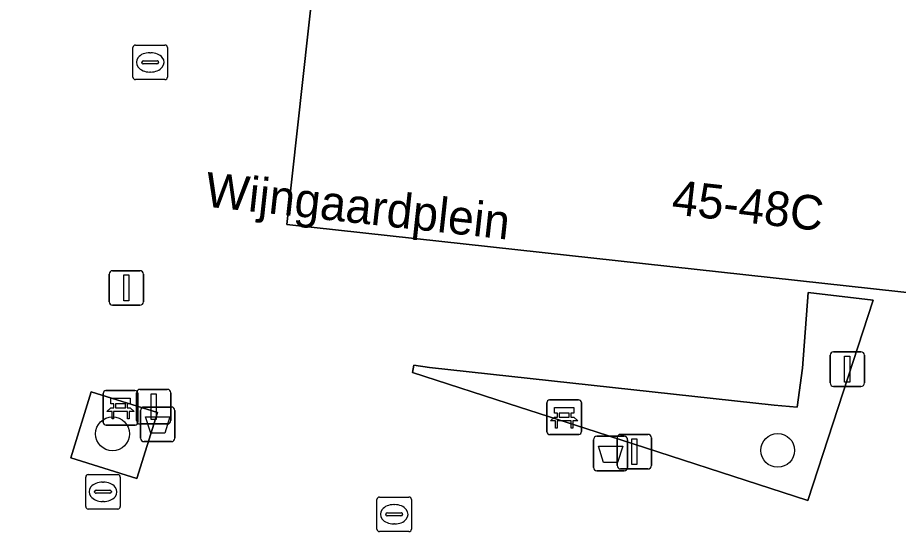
# Model space of a CAD drawing. Extents: x 162026 to 163502, y 387295 to 388169.
# Drawn here: x 162355.04 to 162380.52, y 387587.27 to 387602.42 of the extents above; entities that cross this region are included whole.
import ezdxf

# ---------------------------------------------------------------- set-up
doc = ezdxf.new("R2010")
doc.units = 0
for name, color, linetype in [('IMGEO_Afvalbak', 7, 'Continuous'), ('IMGEO_Bank', 7, 'Continuous'), ('IMGEO_Boom', 7, 'Continuous'), ('IMGEO_Groenvoorziening', 7, 'Continuous'), ('IMGEO_Kolk', 7, 'Continuous'), ('IMGEO_Lichtmast', 7, 'Continuous'), ('IMGEO_Openbare_ruimte_label', 7, 'Continuous'), ('IMGEO_Pand', 7, 'Continuous'), ('IMGEO_Pand_nummerreeks', 7, 'Continuous'), ('IMGEO_Voetpad_open', 7, 'Continuous')]:
    doc.layers.add(name, color=color, linetype=linetype)

msp = doc.modelspace()

# ---------------------------------------------------------------- linework, layer by layer
at = {"layer": 'IMGEO_Afvalbak'}
for p, q in [((162358.598, 387590.256), (162358.598, 387591.056)), ((162358.598, 387591.056), (162358.598, 387590.256)), ((162358.698, 387591.156), (162359.488, 387591.156)), ((162359.488, 387591.156), (162358.698, 387591.156)), ((162359.588, 387591.056), (162359.588, 387590.256)), ((162359.588, 387590.256), (162359.588, 387591.056)), ((162371.795, 387590.31), (162372.585, 387590.31)), ((162372.585, 387590.31), (162371.795, 387590.31)), ((162359.488, 387590.156), (162358.698, 387590.156)), ((162358.698, 387590.156), (162359.488, 387590.156)), ((162371.695, 387589.41), (162371.695, 387590.21)), ((162371.695, 387590.21), (162371.695, 387589.41)), ((162372.685, 387590.21), (162372.685, 387589.41)), ((162372.685, 387589.41), (162372.685, 387590.21)), ((162372.585, 387589.31), (162371.795, 387589.31)), ((162371.795, 387589.31), (162372.585, 387589.31))]:
    msp.add_line(p, q, dxfattribs=at)
for points in [[(162358.741, 387590.87), (162359.445, 387590.87), (162359.296, 387590.4), (162358.89, 387590.4), (162358.741, 387590.87)], [(162371.838, 387590.024), (162372.542, 387590.024), (162372.393, 387589.554), (162371.987, 387589.554), (162371.838, 387590.024)]]:
    msp.add_lwpolyline(points, dxfattribs=at)
for centre, start, end in [((162358.698, 387591.056), 90, 180), ((162358.698, 387591.056), 90, 180), ((162359.488, 387591.056), 0, 90), ((162359.488, 387591.056), 360, 90), ((162358.698, 387590.256), 180, 270), ((162358.698, 387590.256), 180, 270), ((162359.488, 387590.256), 270, 0), ((162359.488, 387590.256), 270, 0), ((162371.795, 387590.21), 90, 180), ((162371.795, 387590.21), 90, 180), ((162372.585, 387590.21), 0, 90), ((162372.585, 387590.21), 360, 90), ((162371.795, 387589.41), 180, 270), ((162371.795, 387589.41), 180, 270), ((162372.585, 387589.41), 270, 0), ((162372.585, 387589.41), 270, 0)]:
    msp.add_arc(centre, 0.1, start, end, dxfattribs=at)
at = {"layer": 'IMGEO_Bank'}
for p, q in [((162357.519, 387590.709), (162357.519, 387591.55)), ((162357.519, 387591.55), (162357.519, 387590.709)), ((162357.594, 387591.634), (162358.435, 387591.634)), ((162358.435, 387591.634), (162357.594, 387591.634)), ((162358.519, 387591.559), (162358.519, 387590.718)), ((162358.519, 387590.718), (162358.519, 387591.559)), ((162357.828, 387591.14), (162357.828, 387591.246)), ((162357.872, 387591.246), (162357.872, 387591.14)), ((162358.16, 387591.252), (162357.878, 387591.252)), ((162358.166, 387591.14), (162358.166, 387591.246)), ((162358.21, 387591.246), (162358.21, 387591.14)), ((162370.349, 387590.437), (162370.349, 387591.278)), ((162370.349, 387591.278), (162370.349, 387590.437)), ((162370.424, 387591.362), (162371.265, 387591.362)), ((162371.265, 387591.362), (162370.424, 387591.362)), ((162371.349, 387591.287), (162371.349, 387590.446)), ((162371.349, 387590.446), (162371.349, 387591.287)), ((162358.216, 387591.032), (162357.823, 387591.032)), ((162357.878, 387591.134), (162358.16, 387591.134)), ((162371.046, 387590.76), (162370.653, 387590.76)), ((162370.658, 387590.868), (162370.658, 387590.974)), ((162370.702, 387590.974), (162370.702, 387590.868)), ((162370.99, 387590.98), (162370.708, 387590.98)), ((162370.708, 387590.862), (162370.99, 387590.862)), ((162370.996, 387590.868), (162370.996, 387590.974)), ((162371.04, 387590.974), (162371.04, 387590.868)), ((162358.444, 387590.634), (162357.603, 387590.634)), ((162357.603, 387590.634), (162358.444, 387590.634)), ((162371.274, 387590.362), (162370.433, 387590.362)), ((162370.433, 387590.362), (162371.274, 387590.362))]:
    msp.add_line(p, q, dxfattribs=at)
for points in [[(162357.822, 387591.252), (162357.736, 387591.252), (162357.736, 387591.413), (162358.299, 387591.413), (162358.299, 387591.252), (162358.216, 387591.252)], [(162357.766, 387591.032), (162357.624, 387591.032), (162357.736, 387591.134), (162357.822, 387591.134)], [(162357.816, 387591.025), (162357.816, 387590.818), (162357.773, 387590.818), (162357.773, 387591.025)], [(162358.216, 387591.134), (162358.299, 387591.134), (162358.411, 387591.032), (162358.272, 387591.032)], [(162358.266, 387591.025), (162358.266, 387590.818), (162358.222, 387590.818), (162358.222, 387591.025)], [(162370.652, 387590.98), (162370.566, 387590.98), (162370.566, 387591.141), (162371.129, 387591.141), (162371.129, 387590.98), (162371.046, 387590.98)], [(162370.596, 387590.76), (162370.454, 387590.76), (162370.566, 387590.862), (162370.652, 387590.862)], [(162370.646, 387590.753), (162370.646, 387590.546), (162370.603, 387590.546), (162370.603, 387590.753)], [(162371.046, 387590.862), (162371.129, 387590.862), (162371.241, 387590.76), (162371.102, 387590.76)], [(162371.096, 387590.753), (162371.096, 387590.546), (162371.052, 387590.546), (162371.052, 387590.753)]]:
    msp.add_lwpolyline(points, dxfattribs=at)
for centre, radius, start, end in [((162357.597, 387591.556), 0.0779, 92.4484, 184.2845), ((162357.597, 387591.556), 0.0779, 92.4484, 184.2845), ((162358.441, 387591.556), 0.0779, 2.4484, 94.2845), ((162358.441, 387591.556), 0.0779, 2.4484, 94.2845), ((162357.821, 387591.245), 0.00671, 2.8957, 87.1043), ((162357.878, 387591.245), 0.00671, 92.8957, 177.1043), ((162358.16, 387591.245), 0.00671, 2.8957, 87.1043), ((162358.217, 387591.245), 0.00671, 92.8957, 177.1043), ((162370.427, 387591.284), 0.0779, 92.4484, 184.2845), ((162370.427, 387591.284), 0.0779, 92.4484, 184.2845), ((162371.271, 387591.284), 0.0779, 2.4484, 94.2845), ((162371.271, 387591.284), 0.0779, 2.4484, 94.2845), ((162357.766, 387591.025), 0.00671, 2.8957, 87.1043), ((162357.823, 387591.025), 0.00671, 92.8957, 177.1043), ((162357.821, 387591.141), 0.00671, 272.8957, 357.1043), ((162357.878, 387591.141), 0.00671, 182.8957, 267.1043), ((162358.16, 387591.141), 0.00671, 272.8957, 357.1043), ((162358.217, 387591.141), 0.00671, 182.8957, 267.1043), ((162358.215, 387591.025), 0.00671, 2.8957, 87.1043), ((162358.272, 387591.025), 0.00671, 92.8957, 177.1043), ((162370.596, 387590.753), 0.00671, 2.8957, 87.1043), ((162370.653, 387590.753), 0.00671, 92.8957, 177.1043), ((162370.651, 387590.973), 0.00671, 2.8957, 87.1043), ((162370.651, 387590.869), 0.00671, 272.8957, 357.1043), ((162370.708, 387590.973), 0.00671, 92.8957, 177.1043), ((162370.708, 387590.869), 0.00671, 182.8957, 267.1043), ((162370.99, 387590.973), 0.00671, 2.8957, 87.1043), ((162370.99, 387590.869), 0.00671, 272.8957, 357.1043), ((162371.047, 387590.973), 0.00671, 92.8957, 177.1043), ((162371.047, 387590.869), 0.00671, 182.8957, 267.1043), ((162371.045, 387590.753), 0.00671, 2.8957, 87.1043), ((162371.102, 387590.753), 0.00671, 92.8957, 177.1043), ((162357.597, 387590.712), 0.0779, 182.4484, 274.2845), ((162357.597, 387590.712), 0.0779, 182.4484, 274.2845), ((162358.441, 387590.712), 0.0779, 272.4484, 4.2845), ((162358.441, 387590.712), 0.0779, 272.4484, 4.2845), ((162370.427, 387590.44), 0.0779, 182.4484, 274.2845), ((162370.427, 387590.44), 0.0779, 182.4484, 274.2845), ((162371.271, 387590.44), 0.0779, 272.4484, 4.2845), ((162371.271, 387590.44), 0.0779, 272.4484, 4.2845)]:
    msp.add_arc(centre, radius, start, end, dxfattribs=at)
at = {"layer": 'IMGEO_Boom'}
for centre in [(162357.787, 387590.381), (162377.026, 387589.902)]:
    msp.add_circle(centre, 0.489, dxfattribs=at)
at = {"layer": 'IMGEO_Groenvoorziening'}
for points in [[(162379.786, 387594.25), (162377.908, 387594.474), (162377.743, 387592.285), (162377.591, 387591.152), (162376.927, 387591.209), (162366.953, 387592.298), (162366.502, 387592.368), (162366.467, 387592.152), (162369.557, 387591.156), (162371.779, 387590.44), (162377.899, 387588.449)], [(162356.577, 387589.687), (162358.486, 387589.091), (162359.083, 387591), (162357.173, 387591.596)]]:
    msp.add_lwpolyline(points, close=True, dxfattribs=at)
at = {"layer": 'IMGEO_Kolk'}
for p, q in [((162358.376, 387600.703), (162358.376, 387601.555)), ((162358.451, 387601.629), (162359.303, 387601.629)), ((162359.377, 387601.555), (162359.377, 387600.703)), ((162358.678, 387601.172), (162359.076, 387601.172)), ((162358.864, 387601.409), (162358.889, 387601.409)), ((162358.635, 387601.123), (162358.635, 387601.135)), ((162359.073, 387601.086), (162358.675, 387601.086)), ((162359.119, 387601.135), (162359.119, 387601.123)), ((162358.887, 387600.849), (162358.862, 387600.849)), ((162359.303, 387600.629), (162358.451, 387600.629)), ((162357.085, 387589.204), (162357.937, 387589.204)), ((162357.01, 387588.278), (162357.01, 387589.13)), ((162357.498, 387588.984), (162357.523, 387588.984)), ((162358.011, 387589.13), (162358.011, 387588.278)), ((162357.269, 387588.698), (162357.269, 387588.71)), ((162357.312, 387588.747), (162357.71, 387588.747)), ((162357.753, 387588.71), (162357.753, 387588.698)), ((162357.707, 387588.661), (162357.309, 387588.661)), ((162365.433, 387587.627), (162365.433, 387588.479)), ((162365.508, 387588.553), (162366.36, 387588.553)), ((162366.434, 387588.479), (162366.434, 387587.627)), ((162357.937, 387588.204), (162357.085, 387588.204)), ((162357.521, 387588.424), (162357.496, 387588.424)), ((162365.921, 387588.333), (162365.946, 387588.333)), ((162365.692, 387588.047), (162365.692, 387588.059)), ((162366.13, 387588.01), (162365.732, 387588.01)), ((162365.735, 387588.096), (162366.133, 387588.096)), ((162366.176, 387588.059), (162366.176, 387588.047)), ((162365.944, 387587.773), (162365.919, 387587.773)), ((162366.36, 387587.553), (162365.508, 387587.553))]:
    msp.add_line(p, q, dxfattribs=at)
for points in [[(162358.376, 387600.703), (162358.376, 387601.555)], [(162358.451, 387601.629), (162359.303, 387601.629)], [(162359.377, 387601.555), (162359.377, 387600.703)], [(162359.303, 387600.629), (162358.451, 387600.629)], [(162357.085, 387589.204), (162357.937, 387589.204)], [(162357.01, 387588.278), (162357.01, 387589.13)], [(162358.011, 387589.13), (162358.011, 387588.278)], [(162365.433, 387587.627), (162365.433, 387588.479)], [(162365.508, 387588.553), (162366.36, 387588.553)], [(162366.434, 387588.479), (162366.434, 387587.627)], [(162357.937, 387588.204), (162357.085, 387588.204)], [(162366.36, 387587.553), (162365.508, 387587.553)]]:
    msp.add_lwpolyline(points, dxfattribs=at)
for centre, radius, start, end in [((162358.453, 387601.553), 0.0765, 91.552, 178.448), ((162358.453, 387601.553), 0.0765, 91.552, 178.448), ((162359.301, 387601.553), 0.0765, 1.552, 88.448), ((162359.301, 387601.553), 0.0765, 1.552, 88.448), ((162358.675, 387601.132), 0.0403, 85.8775, 175.7526), ((162359.08, 387601.134), 0.0386, 1.7309, 96.639), ((162358.672, 387601.122), 0.0366, 178.938, 274.7102), ((162359.076, 387601.129), 0.043, 264.8664, 352.4533), ((162358.453, 387600.705), 0.0765, 181.552, 268.448), ((162358.453, 387600.705), 0.0765, 181.552, 268.448), ((162359.301, 387600.705), 0.0765, 271.552, 358.448), ((162359.301, 387600.705), 0.0765, 271.552, 358.448), ((162357.087, 387589.128), 0.0765, 91.552, 178.448), ((162357.087, 387589.128), 0.0765, 91.552, 178.448), ((162357.935, 387589.128), 0.0765, 1.552, 88.448), ((162357.935, 387589.128), 0.0765, 1.552, 88.448), ((162357.309, 387588.707), 0.0403, 85.8775, 175.7526), ((162357.306, 387588.697), 0.0366, 178.938, 274.7102), ((162357.71, 387588.704), 0.043, 264.8664, 352.4533), ((162357.714, 387588.709), 0.0386, 1.7309, 96.639), ((162365.51, 387588.477), 0.0765, 91.552, 178.448), ((162365.51, 387588.477), 0.0765, 91.552, 178.448), ((162366.358, 387588.477), 0.0765, 1.552, 88.448), ((162366.358, 387588.477), 0.0765, 1.552, 88.448), ((162357.087, 387588.28), 0.0765, 181.552, 268.448), ((162357.087, 387588.28), 0.0765, 181.552, 268.448), ((162357.935, 387588.28), 0.0765, 271.552, 358.448), ((162357.935, 387588.28), 0.0765, 271.552, 358.448), ((162365.732, 387588.056), 0.0403, 85.8775, 175.7526), ((162365.729, 387588.046), 0.0366, 178.938, 274.7102), ((162366.133, 387588.053), 0.043, 264.8664, 352.4533), ((162366.137, 387588.058), 0.0386, 1.7309, 96.639), ((162365.51, 387587.629), 0.0765, 181.552, 268.448), ((162365.51, 387587.629), 0.0765, 181.552, 268.448), ((162366.358, 387587.629), 0.0765, 271.552, 358.448), ((162366.358, 387587.629), 0.0765, 271.552, 358.448)]:
    msp.add_arc(centre, radius, start, end, dxfattribs=at)
for centre, major_axis, ratio, start_param, end_param in [((162358.863, 387601.129), (-0.387, 0.002), 0.722429, 4.712389, 7.853982), ((162358.888, 387601.129), (-0.39, 0.002), 0.717154, 1.570796, 4.712389), ((162357.497, 387588.704), (-0.387, 0.002), 0.722429, 4.712389, 7.853982), ((162357.522, 387588.704), (-0.39, 0.002), 0.717154, 1.570796, 4.712389), ((162365.92, 387588.053), (-0.387, 0.002), 0.722429, 4.712389, 7.853982), ((162365.945, 387588.053), (-0.39, 0.002), 0.717154, 1.570796, 4.712389)]:
    msp.add_ellipse(centre, major_axis=major_axis, ratio=ratio, start_param=start_param, end_param=end_param, dxfattribs=at)
at = {"layer": 'IMGEO_Lichtmast'}
for p, q in [((162357.789, 387595.102), (162358.579, 387595.102)), ((162358.579, 387595.102), (162357.789, 387595.102)), ((162357.689, 387594.202), (162357.689, 387595.002)), ((162357.689, 387595.002), (162357.689, 387594.202)), ((162358.679, 387595.002), (162358.679, 387594.202)), ((162358.679, 387594.202), (162358.679, 387595.002)), ((162358.579, 387594.102), (162357.789, 387594.102)), ((162357.789, 387594.102), (162358.579, 387594.102)), ((162378.542, 387591.854), (162378.542, 387592.654)), ((162378.542, 387592.654), (162378.542, 387591.854)), ((162378.642, 387592.754), (162379.432, 387592.754)), ((162379.432, 387592.754), (162378.642, 387592.754)), ((162379.532, 387592.654), (162379.532, 387591.854)), ((162379.532, 387591.854), (162379.532, 387592.654)), ((162379.432, 387591.754), (162378.642, 387591.754)), ((162378.642, 387591.754), (162379.432, 387591.754)), ((162358.481, 387590.767), (162358.481, 387591.567)), ((162358.481, 387591.567), (162358.481, 387590.767)), ((162358.581, 387591.667), (162359.371, 387591.667)), ((162359.371, 387591.667), (162358.581, 387591.667)), ((162359.471, 387591.567), (162359.471, 387590.767)), ((162359.471, 387590.767), (162359.471, 387591.567)), ((162359.371, 387590.667), (162358.581, 387590.667)), ((162358.581, 387590.667), (162359.371, 387590.667)), ((162372.382, 387589.465), (162372.382, 387590.265)), ((162372.382, 387590.265), (162372.382, 387589.465)), ((162372.482, 387590.365), (162373.272, 387590.365)), ((162373.272, 387590.365), (162372.482, 387590.365)), ((162373.372, 387590.265), (162373.372, 387589.465)), ((162373.372, 387589.465), (162373.372, 387590.265)), ((162373.272, 387589.365), (162372.482, 387589.365)), ((162372.482, 387589.365), (162373.272, 387589.365))]:
    msp.add_line(p, q, dxfattribs=at)
for points in [[(162358.109, 387594.977), (162358.259, 387594.977), (162358.259, 387594.227), (162358.109, 387594.227), (162358.109, 387594.977)], [(162378.962, 387592.629), (162379.112, 387592.629), (162379.112, 387591.879), (162378.962, 387591.879), (162378.962, 387592.629)], [(162358.901, 387591.542), (162359.051, 387591.542), (162359.051, 387590.792), (162358.901, 387590.792), (162358.901, 387591.542)], [(162372.802, 387590.24), (162372.952, 387590.24), (162372.952, 387589.49), (162372.802, 387589.49), (162372.802, 387590.24)]]:
    msp.add_lwpolyline(points, dxfattribs=at)
for centre, start, end in [((162357.789, 387595.002), 90, 180), ((162357.789, 387595.002), 90, 180), ((162358.579, 387595.002), 0, 90), ((162358.579, 387595.002), 360, 90), ((162357.789, 387594.202), 180, 270), ((162357.789, 387594.202), 180, 270), ((162358.579, 387594.202), 270, 0), ((162358.579, 387594.202), 270, 0), ((162378.642, 387592.654), 90, 180), ((162378.642, 387592.654), 90, 180), ((162379.432, 387592.654), 0, 90), ((162379.432, 387592.654), 360, 90), ((162378.642, 387591.854), 180, 270), ((162378.642, 387591.854), 180, 270), ((162379.432, 387591.854), 270, 0), ((162379.432, 387591.854), 270, 0), ((162358.581, 387591.567), 90, 180), ((162358.581, 387591.567), 90, 180), ((162359.371, 387591.567), 0, 90), ((162359.371, 387591.567), 360, 90), ((162358.581, 387590.767), 180, 270), ((162358.581, 387590.767), 180, 270), ((162359.371, 387590.767), 270, 0), ((162359.371, 387590.767), 270, 0), ((162372.482, 387590.265), 90, 180), ((162372.482, 387590.265), 90, 180), ((162373.272, 387590.265), 0, 90), ((162373.272, 387590.265), 360, 90), ((162372.482, 387589.465), 180, 270), ((162372.482, 387589.465), 180, 270), ((162373.272, 387589.465), 270, 0), ((162373.272, 387589.465), 270, 0)]:
    msp.add_arc(centre, 0.1, start, end, dxfattribs=at)
at = {"layer": 'IMGEO_Pand'}
msp.add_lwpolyline([(162364.534, 387611.918), (162362.831, 387596.441), (162383.487, 387594.169), (162386.349, 387593.854), (162387.447, 387603.869), (162407.859, 387601.627), (162407.825, 387601.316), (162407.369, 387597.19), (162409, 387597.009), (162412.477, 387596.624), (162413.501, 387605.868)], dxfattribs=at)
at = {"layer": 'IMGEO_Voetpad_open'}
for points in [[(162364.534, 387611.918), (162365.431, 387620.069), (162356.362, 387620.977), (162355.852, 387616.592), (162351.943, 387582.961), (162352.454, 387582.905), (162360.935, 387581.973), (162373.768, 387580.561), (162373.225, 387575.616), (162370.078, 387547.752), (162369.725, 387544.71), (162370.028, 387544.676), (162377.504, 387543.833), (162377.835, 387543.796), (162383.487, 387594.169), (162362.831, 387596.441)], [(162379.786, 387594.25), (162377.899, 387588.449), (162371.779, 387590.44), (162369.557, 387591.156), (162366.467, 387592.152), (162366.502, 387592.368), (162366.953, 387592.298), (162376.927, 387591.209), (162377.591, 387591.152), (162377.743, 387592.285), (162377.908, 387594.474)], [(162359.083, 387591), (162358.486, 387589.091), (162356.577, 387589.687), (162357.173, 387591.596)]]:
    msp.add_lwpolyline(points, close=True, dxfattribs=at)

# ---------------------------------------------------------------- texts
at = {"layer": 'IMGEO_Openbare_ruimte_label'}
msp.add_text('Wijngaardplein', height=1, rotation=353.7421, dxfattribs=at).set_placement((162360.43, 387596.963))
at = {"layer": 'IMGEO_Pand_nummerreeks'}
msp.add_text('45-48C', height=1, rotation=353.5256, dxfattribs=at).set_placement((162373.934, 387596.739))

doc.saveas('drawing.dxf')
